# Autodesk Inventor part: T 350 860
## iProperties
Company: Mayer & Müller AG Schaltgeräte
Created: 2006-03
Part Number: T 350 860
Material: 2.0040.26
Document SubType Name: Modeling
Designer: I.Baliuc
Description: Stromschiene, unten
Density: 8.94 g/cm^3
HalbzeugNorm: DIN 1759
Zweck: für Vorkontakt HSLT
Abmessung: Fl. 120 x 15 - 222
Author: T.Messerschmitt
Keywords: 382024
Revision Number: 350860
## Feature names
1. 80 x 15 - 222 [Extrusion]
2. Bohrung_Ø10.5 [Hole]
3. Bohrung_Ø6.5 [Hole]
4. Bohrung_M6 [Hole]
